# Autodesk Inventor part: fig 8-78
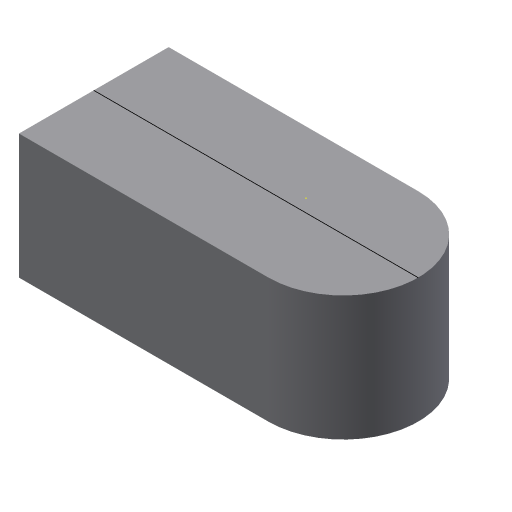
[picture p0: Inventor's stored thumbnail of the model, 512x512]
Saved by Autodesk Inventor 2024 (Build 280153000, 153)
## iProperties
Created: 2011-07
Part Number: fig 8-78
Material: Generic
Document SubType Name: Modeling
Designer: CadCim
Density: 1 g/cm^3
Appearance: Default
Author: CadCim
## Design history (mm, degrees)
sketch "Sketch1"
  geometry: L1 (-16, 5)-(-16, -7); L2 (-16, -7)-(4, -7); L3 (4, 5)-(-16, 5); A1 r 6 centre (4, -1) between (4, -7) and (4, 5); 1 further point
  constraints: 6 end point, 2 point on circle, 2 tangent, 1 centre point, 1 parallel, 1 perpendicular, 1 vertical
extrude "Extrusion1" new body sketch "Sketch1" distance "d0" = 10; taper "d1" = 0 deg
sketch "Sketch2"
  geometry: L1 (-16, -1)-(10, -1); 1 further point
  constraints: 2 end point, 1 horizontal
body "Solid1"
